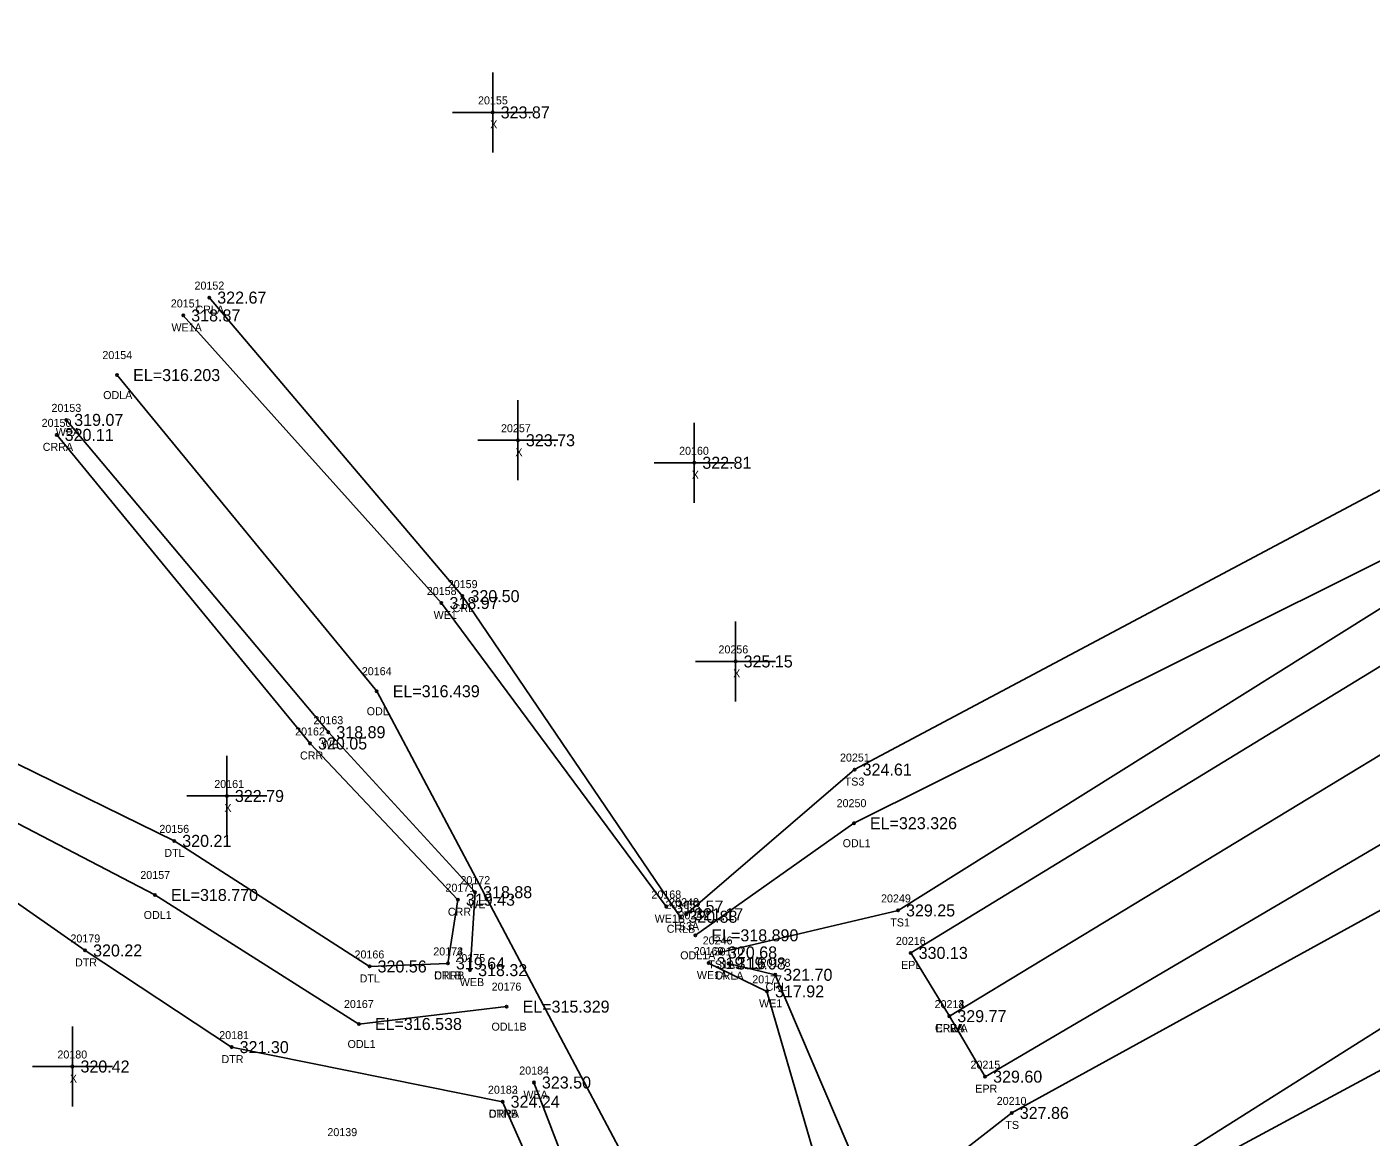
# Model space of a CAD drawing. Extents: x 2231109 to 2232328, y 1035718 to 1036919.
# Drawn here: x 2231490.9 to 2231658.8, y 1036447.8 to 1036586.5 of the extents above; entities that cross this region are included whole.
import ezdxf

# ---------------------------------------------------------------- set-up
doc = ezdxf.new("R2010")
doc.units = 0
for name, color, linetype in [('RD_DTM_BkLn1', 7, 'Continuous'), ('RD_DTM_BkLn2', 7, 'Continuous'), ('RD_DTM_BkLn_txCode', 7, 'Continuous'), ('RD_EX_H2O', 7, 'Continuous'), ('RD_EX_H2O_txCode', 7, 'Continuous'), ('RD_EX_Misc', 7, 'Continuous'), ('RD_EX_Misc_txCode', 7, 'Continuous'), ('RD_EX_Road', 7, 'Continuous'), ('RD_EX_Road_txCode', 7, 'Continuous'), ('RD_EX_TX_H2O_ELEV', 7, 'Continuous'), ('RD_EX_TX_Misc_ELEV', 7, 'Continuous'), ('RD_EX_TX_Road_ELEV', 7, 'Continuous'), ('RD_HC_Survey_ELEV', 7, 'Continuous'), ('RD_HC_Survey_txCode', 7, 'Continuous'), ('RD_SMD_Locator', 7, 'Continuous')]:
    doc.layers.add(name, color=color, linetype=linetype)

msp = doc.modelspace()

# ---------------------------------------------------------------- linework, layer by layer
at = {"layer": 'RD_DTM_BkLn1'}
msp.add_lwpolyline([(2231606.1, 1036462.92), (2231686.87, 1036511.89), (2231772.7, 1036562.84), (2231856.39, 1036612), (2231941.22, 1036662.52), (2232026.21, 1036712.41), (2232112.3, 1036762.07), (2232195.17, 1036811.63), (2232281.68, 1036862.71)], dxfattribs=at)
at = {"layer": 'RD_DTM_BkLn2'}
for points in [[(2231573.22, 1036475.66), (2231594.27, 1036493.73), (2231671.78, 1036534.98), (2231709.57, 1036556.01), (2231719.34, 1036556.5)], [(2231577.44, 1036470.88), (2231599.69, 1036476.13), (2231678.5, 1036525.49), (2231694.89, 1036533.9), (2231719.34, 1036556.5)], [(2231593.79, 1036430.95), (2231605.6, 1036444.4), (2231613.9, 1036450.83), (2231692.8, 1036494.19), (2231698.97, 1036489.96), (2231701.87, 1036483.3), (2231696.9, 1036476.1), (2231598.32, 1036422.92)]]:
    msp.add_lwpolyline(points, dxfattribs=at)
at = {"layer": 'RD_EX_H2O'}
for points in [[(2231574.37, 1036473.02), (2231594.18, 1036487.03), (2231675.14, 1036527.33), (2231719.34, 1036556.5)], [(2231513.64, 1036552.7), (2231545.27, 1036515.4), (2231572.49, 1036475.34)], [(2231510.39, 1036550.47), (2231542.65, 1036514.54), (2231570.74, 1036476.62)], [(2231502.13, 1036543.02), (2231534.56, 1036503.52), (2231575.4, 1036426.58), (2231579.81, 1036378.35), (2231570.46, 1036330.21)], [(2231495.77, 1036537.42), (2231528.52, 1036498.4), (2231546.85, 1036478.41), (2231546.23, 1036468.67)], [(2231494.58, 1036535.55), (2231526.23, 1036496.99), (2231544.7, 1036477.47), (2231543.46, 1036469.51)], [(2231470.16, 1036504), (2231509.27, 1036484.82), (2231533.67, 1036469.13), (2231543.46, 1036469.51)], [(2231468.56, 1036497.99), (2231506.86, 1036478.06), (2231532.33, 1036461.94), (2231550.78, 1036464.11)], [(2231466.58, 1036493.16), (2231498.13, 1036471.13), (2231516.44, 1036459.05), (2231550.29, 1036452.23)], [(2231595.07, 1036425.7), (2231623.2, 1036438.12), (2231694.44, 1036483.11)], [(2231576.03, 1036469.55), (2231583.32, 1036466.02), (2231591.59, 1036437.46), (2231594.64, 1036426.26)], [(2231578.53, 1036469.5), (2231584.36, 1036468.09), (2231596.48, 1036439.6), (2231593.95, 1036431.64)], [(2231554.2, 1036454.63), (2231567.2, 1036420.78), (2231573.56, 1036381.32), (2231561.13, 1036328.97)], [(2231550.29, 1036452.23), (2231565.49, 1036418.12), (2231564.98, 1036385.4), (2231555.04, 1036329.79)]]:
    msp.add_lwpolyline(points, dxfattribs=at)
at = {"layer": 'RD_EX_Misc'}
for p, q in [((2231549.05, 1036570.84), (2231549.05, 1036580.84)), ((2231544.05, 1036575.84), (2231554.05, 1036575.84)), ((2231552.2, 1036529.88), (2231552.2, 1036539.88)), ((2231574.24, 1036527.06), (2231574.24, 1036537.06)), ((2231547.2, 1036534.88), (2231557.2, 1036534.88)), ((2231569.24, 1036532.06), (2231579.24, 1036532.06)), ((2231579.4, 1036502.24), (2231579.4, 1036512.24)), ((2231574.4, 1036507.24), (2231584.4, 1036507.24)), ((2231515.84, 1036485.43), (2231515.84, 1036495.43)), ((2231510.84, 1036490.43), (2231520.84, 1036490.43)), ((2231496.55, 1036451.63), (2231496.55, 1036461.63)), ((2231491.55, 1036456.63), (2231501.55, 1036456.63))]:
    msp.add_line(p, q, dxfattribs=at)
at = {"layer": 'RD_EX_Road'}
for points in [[(2231606.1, 1036462.92), (2231601.27, 1036470.82), (2231681.58, 1036519.84), (2231764.99, 1036568.78), (2231851.5, 1036619.95), (2231935.62, 1036669.65), (2232021.78, 1036720.22), (2232106.75, 1036770.57), (2232190.54, 1036819.2), (2232275.92, 1036870.27)], [(2231606.1, 1036462.92), (2231610.57, 1036455.36), (2231692.09, 1036503.24), (2231706.07, 1036512.59), (2231777.1, 1036553.27), (2231861.39, 1036604.65), (2231946.39, 1036654.77), (2232031.07, 1036704.2), (2232117.06, 1036755.16), (2232199.91, 1036803.8), (2232286.7, 1036855.36)]]:
    msp.add_lwpolyline(points, dxfattribs=at)
at = {"layer": 'RD_SMD_Locator'}
for centre in [(2231549.05, 1036575.84), (2231513.64, 1036552.7), (2231510.39, 1036550.47), (2231502.13, 1036543.02), (2231495.77, 1036537.42), (2231494.58, 1036535.55), (2231552.2, 1036534.88), (2231574.24, 1036532.06), (2231545.27, 1036515.4), (2231542.65, 1036514.54), (2231579.4, 1036507.24), (2231534.56, 1036503.52), (2231528.52, 1036498.4), (2231526.23, 1036496.99), (2231594.27, 1036493.73), (2231515.84, 1036490.43), (2231594.18, 1036487.03), (2231509.27, 1036484.82), (2231506.86, 1036478.06), (2231546.85, 1036478.41), (2231544.7, 1036477.47), (2231570.74, 1036476.62), (2231599.69, 1036476.13), (2231572.49, 1036475.34), (2231573.22, 1036475.66), (2231574.37, 1036473.02), (2231498.13, 1036471.13), (2231543.46, 1036469.51), (2231543.46, 1036469.51), (2231576.03, 1036469.55), (2231577.44, 1036470.88), (2231578.53, 1036469.5), (2231601.27, 1036470.82), (2231533.67, 1036469.13), (2231546.23, 1036468.67), (2231584.36, 1036468.09), (2231583.32, 1036466.02), (2231550.78, 1036464.11), (2231606.1, 1036462.92), (2231606.1, 1036462.92), (2231606.1, 1036462.92), (2231532.33, 1036461.94), (2231516.44, 1036459.05), (2231496.55, 1036456.63), (2231554.2, 1036454.63), (2231610.57, 1036455.36), (2231550.29, 1036452.23), (2231550.29, 1036452.23), (2231613.9, 1036450.83)]:
    msp.add_circle(centre, 0.15, dxfattribs=at)

# ---------------------------------------------------------------- texts
at = {"layer": 'RD_DTM_BkLn_txCode'}
for s, p in [('20251', (2231592.44, 1036494.73)), ('TS3', (2231593.03, 1036491.73)), ('20249', (2231597.57, 1036477.13)), ('20248', (2231571.1, 1036476.66)), ('TS3A', (2231571.49, 1036473.66)), ('TS1', (2231598.72, 1036474.13)), ('20246', (2231575.29, 1036471.88)), ('TS1A', (2231575.99, 1036468.88)), ('20210', (2231612.02, 1036451.83)), ('TS', (2231613.1, 1036448.83)), ('20139', (2231528.4, 1036447.93))]:
    msp.add_text(s, height=1, dxfattribs=at).set_placement(p)
at = {"layer": 'RD_EX_H2O_txCode'}
for s, p in [('20152', (2231511.8, 1036553.7)), ('20151', (2231508.84, 1036551.47)), ('CRLA', (2231511.92, 1036550.7)), ('WE1A', (2231508.92, 1036548.47)), ('20154', (2231500.29, 1036545.02)), ('ODLA', (2231500.39, 1036540.02)), ('20153', (2231493.93, 1036538.42)), ('20150', (2231492.7, 1036536.55)), ('WEA', (2231494.46, 1036535.42)), ('CRRA', (2231492.84, 1036533.55)), ('20158', (2231540.82, 1036515.54)), ('20159', (2231543.44, 1036516.4)), ('WE1', (2231541.67, 1036512.54)), ('CRL', (2231544.05, 1036513.4)), ('20164', (2231532.7, 1036505.52)), ('ODL', (2231533.31, 1036500.52)), ('20163', (2231526.66, 1036499.4)), ('20162', (2231524.37, 1036497.99)), ('WE', (2231527.68, 1036496.4)), ('CRR', (2231524.98, 1036494.99)), ('20250', (2231592.02, 1036489.03)), ('20156', (2231507.41, 1036485.82)), ('ODL1', (2231592.77, 1036484.03)), ('DTL', (2231508.03, 1036482.82)), ('20157', (2231505.03, 1036480.06)), ('20171', (2231543.15, 1036478.47)), ('20172', (2231545.02, 1036479.41)), ('20168', (2231568.88, 1036477.62)), ('CRR', (2231543.45, 1036475.47)), ('WE', (2231546.01, 1036476.41)), ('20165', (2231570.63, 1036476.34)), ('ODL1', (2231505.45, 1036475.06)), ('WE1B', (2231569.29, 1036474.62)), ('20247', (2231572.26, 1036475.02)), ('20179', (2231496.3, 1036472.13)), ('CRLB', (2231570.79, 1036473.34)), ('20166', (2231531.79, 1036470.13)), ('20173', (2231541.63, 1036470.51)), ('20174', (2231541.63, 1036470.51)), ('20169', (2231574.17, 1036470.55)), ('20170', (2231576.66, 1036470.5)), ('DTR', (2231496.87, 1036469.13)), ('20175', (2231544.39, 1036469.67)), ('ODL1A', (2231572.48, 1036470.02)), ('20178', (2231582.53, 1036469.09)), ('DTL', (2231532.43, 1036467.13)), ('CRRB', (2231541.74, 1036467.51)), ('DTLB', (2231541.75, 1036467.51)), ('WE1A', (2231574.56, 1036467.55)), ('CRLA', (2231576.81, 1036467.5)), ('20177', (2231581.48, 1036467.02)), ('WEB', (2231544.94, 1036466.67)), ('20176', (2231548.92, 1036466.11)), ('CRL', (2231583.14, 1036466.09)), ('20167', (2231530.47, 1036463.94)), ('WE1', (2231582.33, 1036464.02)), ('20181', (2231514.89, 1036460.05)), ('ODL1B', (2231548.9, 1036461.11)), ('ODL1', (2231530.92, 1036458.94)), ('DTR', (2231515.17, 1036457.05)), ('20184', (2231552.37, 1036455.63)), ('20182', (2231548.46, 1036453.23)), ('20183', (2231548.46, 1036453.23)), ('WEA', (2231552.89, 1036452.63)), ('CRRA', (2231548.55, 1036450.23)), ('DTRB', (2231548.55, 1036450.23))]:
    msp.add_text(s, height=1, dxfattribs=at).set_placement(p)
at = {"layer": 'RD_EX_Misc_txCode'}
for s, p in [('20155', (2231547.22, 1036576.84)), ('X', (2231548.74, 1036573.84)), ('20257', (2231550.09, 1036535.88)), ('X', (2231551.89, 1036532.88)), ('20160', (2231572.34, 1036533.06)), ('X', (2231573.92, 1036530.06)), ('20256', (2231577.26, 1036508.24)), ('X', (2231579.09, 1036505.24)), ('20161', (2231514.27, 1036491.43)), ('X', (2231515.53, 1036488.43)), ('20180', (2231494.67, 1036457.63)), ('X', (2231496.23, 1036454.63))]:
    msp.add_text(s, height=1, dxfattribs=at).set_placement(p)
at = {"layer": 'RD_EX_Road_txCode'}
for s, p in [('20216', (2231599.42, 1036471.82)), ('EPL', (2231600.07, 1036468.82)), ('20213', (2231604.26, 1036463.92)), ('20214', (2231604.26, 1036463.92)), ('EPRA', (2231604.38, 1036460.92)), ('EPLA', (2231604.41, 1036460.92)), ('20215', (2231608.74, 1036456.36)), ('EPR', (2231609.34, 1036453.36))]:
    msp.add_text(s, height=1, dxfattribs=at).set_placement(p)
at = {"layer": 'RD_EX_TX_H2O_ELEV'}
for s, p in [('322.67', (2231514.64, 1036551.95)), ('318.87', (2231511.39, 1036549.72)), ('EL=316.203', (2231504.13, 1036542.27)), ('319.07', (2231496.77, 1036536.67)), ('320.11', (2231495.58, 1036534.8)), ('318.97', (2231543.65, 1036513.79)), ('320.50', (2231546.27, 1036514.65)), ('EL=316.439', (2231536.56, 1036502.77)), ('318.89', (2231529.52, 1036497.65)), ('320.05', (2231527.23, 1036496.24)), ('EL=323.326', (2231596.18, 1036486.28)), ('320.21', (2231510.27, 1036484.07)), ('EL=318.770', (2231508.86, 1036477.31)), ('319.43', (2231545.7, 1036476.72)), ('318.88', (2231547.85, 1036477.66)), ('318.57', (2231571.74, 1036475.87)), ('320.88', (2231573.49, 1036474.59)), ('EL=318.890', (2231576.37, 1036472.27)), ('320.22', (2231499.13, 1036470.38)), ('320.56', (2231534.67, 1036468.38)), ('319.64', (2231544.46, 1036468.76)), ('319.64', (2231544.46, 1036468.76)), ('318.32', (2231547.23, 1036467.92)), ('319.16', (2231577.03, 1036468.8)), ('319.98', (2231579.53, 1036468.75)), ('321.70', (2231585.36, 1036467.34)), ('317.92', (2231584.32, 1036465.27)), ('EL=315.329', (2231552.78, 1036463.36)), ('EL=316.538', (2231534.33, 1036461.19)), ('321.30', (2231517.44, 1036458.3)), ('323.50', (2231555.2, 1036453.88)), ('324.24', (2231551.29, 1036451.48)), ('324.24', (2231551.29, 1036451.48))]:
    msp.add_text(s, height=1.5, dxfattribs=at).set_placement(p)
at = {"layer": 'RD_EX_TX_Misc_ELEV'}
for s, p in [('323.87', (2231550.05, 1036575.09)), ('323.73', (2231553.2, 1036534.13)), ('322.81', (2231575.24, 1036531.31)), ('325.15', (2231580.4, 1036506.49)), ('324.61', (2231595.27, 1036492.98)), ('322.79', (2231516.84, 1036489.68)), ('321.17', (2231574.22, 1036474.91)), ('329.25', (2231600.69, 1036475.38)), ('320.68', (2231578.44, 1036470.13)), ('320.42', (2231497.55, 1036455.88)), ('327.86', (2231614.9, 1036450.08))]:
    msp.add_text(s, height=1.5, dxfattribs=at).set_placement(p)
at = {"layer": 'RD_EX_TX_Road_ELEV'}
for s, p in [('330.13', (2231602.27, 1036470.07)), ('329.77', (2231607.1, 1036462.17)), ('329.77', (2231607.1, 1036462.17)), ('329.60', (2231611.57, 1036454.61))]:
    msp.add_text(s, height=1.5, dxfattribs=at).set_placement(p)
at = {"layer": 'RD_HC_Survey_ELEV'}
msp.add_text('329.77', height=1.5, dxfattribs=at).set_placement((2231607.1, 1036462.17))
at = {"layer": 'RD_HC_Survey_txCode'}
for s, p in [('20212', (2231604.26, 1036463.92)), ('CRWA', (2231604.3, 1036460.92))]:
    msp.add_text(s, height=1, dxfattribs=at).set_placement(p)

doc.saveas('drawing.dxf')
